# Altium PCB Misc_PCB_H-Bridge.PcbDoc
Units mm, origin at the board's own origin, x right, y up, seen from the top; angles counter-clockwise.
Board outline 25.4 x 30.58 mm, 2 copper layers (Top Layer, Bottom Layer); 16 components, 10 nets, 49 pads, 5 vias.
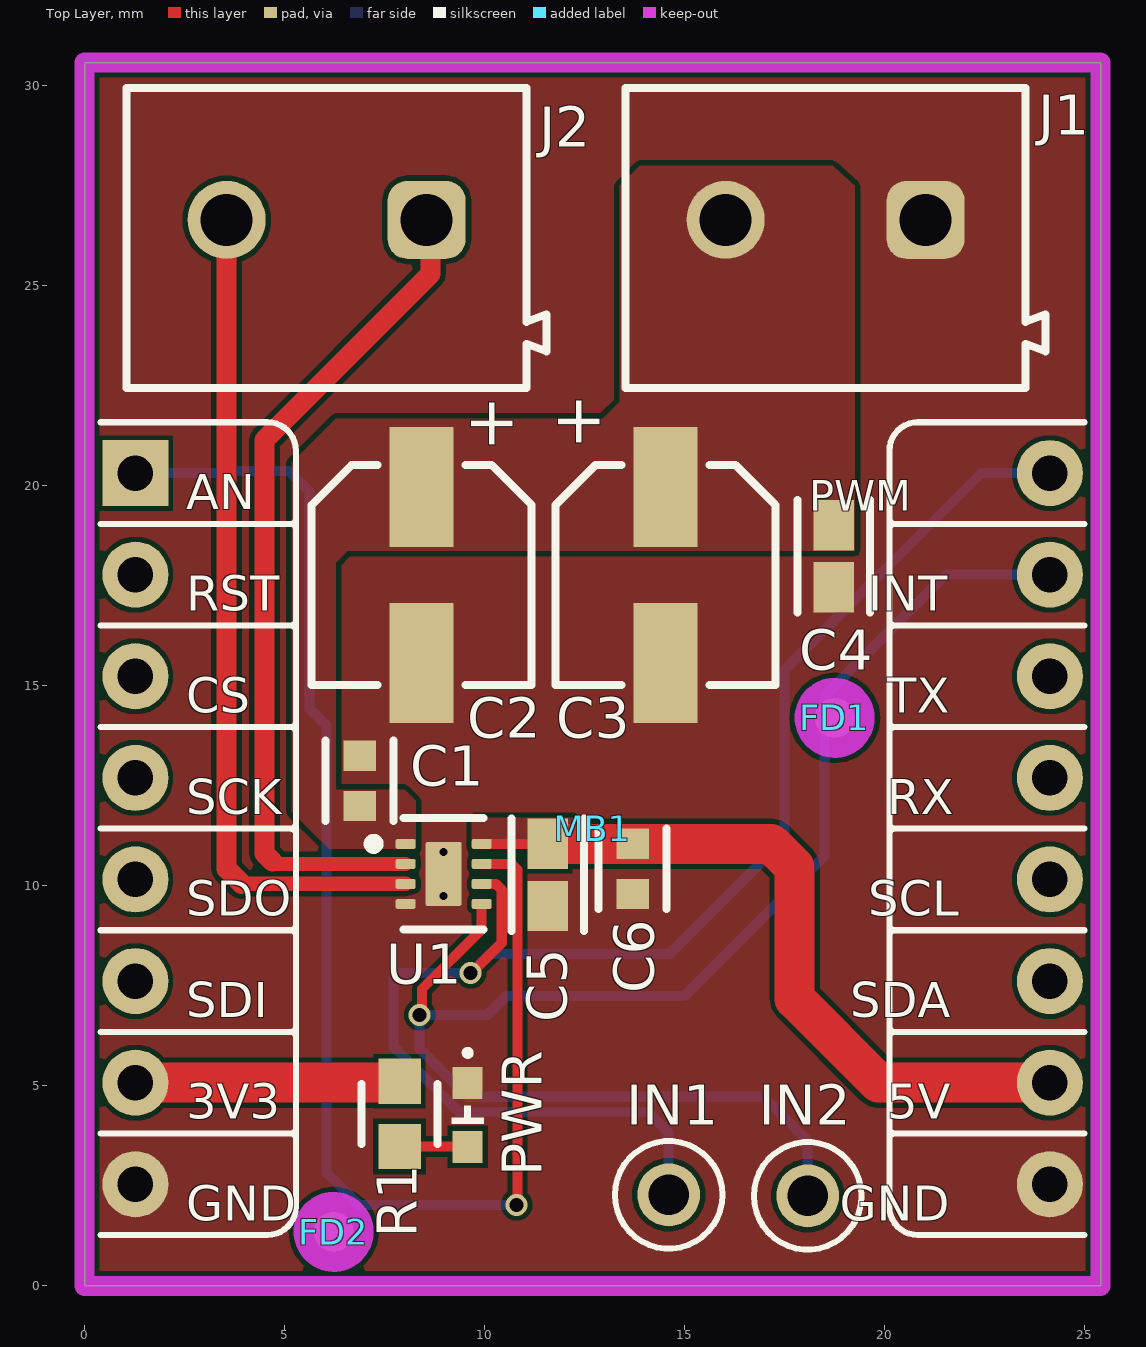
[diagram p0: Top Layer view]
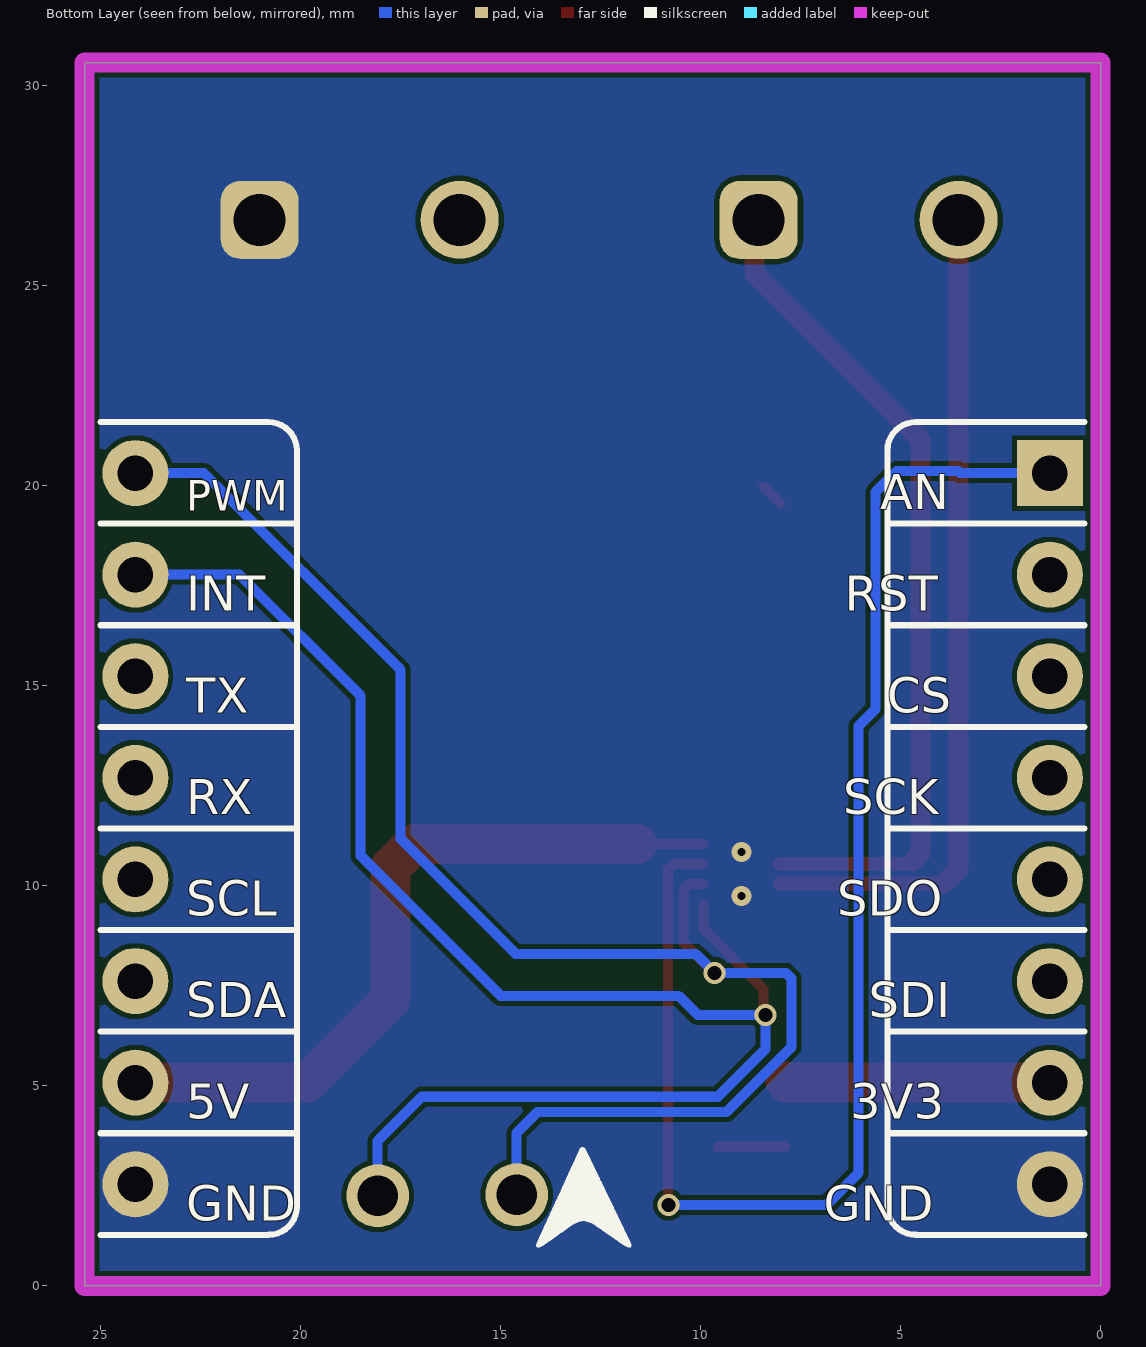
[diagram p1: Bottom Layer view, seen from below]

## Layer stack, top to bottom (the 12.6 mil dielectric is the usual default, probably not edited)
Top Solder: solder mask 0.0102, Solder Resist, Dk 3.5
Top Layer: signal copper 0.0356
Dielectric 1: dielectric 0.32, FR-4, Dk 4.8
Bottom Layer: signal copper 0.0356
Bottom Solder: solder mask 0.0102, Solder Resist, Dk 3.5

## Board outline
0,0 0,30.58 25.4,30.58 25.4,0

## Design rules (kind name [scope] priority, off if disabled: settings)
Clearance [All] p1: gap=0.125 ignorepadtopadclearanceinfootprint=FALSE
HoleSize HoleSizeVia [IsVia] p1: absolutevalues=TRUE maxlimit=0.45 minlimit=0.25 maxpercent=80.000 minpercent=20.000
HoleSize HoleSizePTH [IsPad] p2: absolutevalues=TRUE maxlimit=5.6 minlimit=0.5 maxpercent=80.000 minpercent=20.000
HoleToHoleClearance [All] p1: gap=0.3 allowstackedmicrovias=TRUE
MinimumAnnularRing MinimumAnnularRingVias [All] p1: minimumring=0.1
MinimumAnnularRing MinimumAnnularRingGeneral [All] p2: minimumring=0.3
MinimumSolderMaskSliver [All] p1: minsoldermaskwidth=0.08
PasteMaskExpansion [All] p1: expansion=0.085
PolygonConnect [All] p1: connectstyle=Direct reliefconductorwidth=0.254 reliefentries=4 polygonreliefangle="90 Angle" airgapwidth=0.254
RoutingVias [All] p1: holewidth=0.35 width=0.55 viastyle="Through Hole" minholewidth=0.3 minwidth=0.5 maxholewidth=0.45 maxwidth=0.65
SilkToSilkClearance SilkToSilkClerance [All] p1: silktosilkclearance=0.125
SilkToSolderMaskClearance [IsPad] p1: minsilkscreentomaskgap=0.125 clearancetoexposedcopper=TRUE
SolderMaskExpansion SolderMaskExpansionVia [IsVia] p1: expansion=0.1 istentingtop=TRUE useseparateexpansions=TRUE expansionbottom=0.1 istentingbottom=TRUE
SolderMaskExpansion [All] p2: expansion=0.075 istentingtop=FALSE
SupplyNets "Schematic Supply Nets_3" [InNet('VMotor')] p1: voltage=0.000
SupplyNets "Schematic Supply Nets_2" [InNet('+3V3')] p2: voltage=0.000
SupplyNets "Schematic Supply Nets_1" [InNet('GND')] p3: voltage=0.000
SupplyNets "Schematic Supply Nets" [InNet('+5')] p4: voltage=0.000
UnRoutedNet [All] p1: checkbadconnections=TRUE
Width [All] p1: maxlimit=2.54 minlimit=0.125 preferedwidth=0.254
23 further rules are at their usual default settings.

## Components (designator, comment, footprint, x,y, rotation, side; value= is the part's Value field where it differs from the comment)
C1 "4.7uF" FP-CL10-IPC_C 6.875,12.625 r90 top
C2 "10uF" WCAP-ASLI_D5H5.5 8.425,17.775 r90 top
C3 "10uF" WCAP-ASLI_D5H5.5 14.522,17.775 r90 top
C4 "0.1uF" FP-CC0603-DA-IPC_A 18.725,18.242 r90 top
C5 "0.1uF" FP-CC0603-DA-IPC_A 11.575,10.275 r90 top
C6 "4.7uF" FP-CL10-IPC_C 13.7,10.425 r270 top
FD1 "FID1X2R" FID1X2R 18.75,14.2 r0 top
FD2 "FID1X2R" FID1X2R 6.225,1.35 r90 top
IN1 "5001" FP-5001-MFG 14.6,2.275 r0 top
IN2 "5001" FP-5001-MFG 18.075,2.25 r90 top
J1 "691502710002" 691502710002 18.525,26.2 r180 top
J2 "691502710002" 691502710002 6.05,26.2 r180 top
MB1 "Embedd_Sensor_Schields" "Embedd_add_on_board_25,4 x 30,58" 0,0 r0 top locked
PWR "150060GS55040" WL-SMCD_0603 1279.575,-1265.725 r270 top (schematic designator PWR1)
R1 "33" FP-CRCW0603-e3-IPC_A 7.875,4.3 r90 top
U1 "DRV8210PDSGR" FP-DSG0008A-MFG 8.975,10.3 r0 top

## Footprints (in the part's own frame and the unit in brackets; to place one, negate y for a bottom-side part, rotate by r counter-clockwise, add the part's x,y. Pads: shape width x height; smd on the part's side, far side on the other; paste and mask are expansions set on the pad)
691502710002 [mm] "5,00mm - modular - Reflow compatible - Horizontal entry with pressure clamp - 02p"
  rrect50% 1.95x1.95 hole 1.3: 1(-2.5,-0.45)
  round 1.95 hole 1.3: 2(2.5,-0.45)
  silkscreen extent -5.5,-3.75 5,3.75, body extent -5.5,-3.75 5,3.75, height 10.1
"Embedd_add_on_board_25,4 x 30,58" [mil] "Medium footprint"
  rect 65x65 hole 35: 1(50,800)
  round 65 hole 35: 2(50,700) 3(50,600) 4(50,500) 5(50,400) 6(50,300) 7(50,200) 8(50,100) 9(950,100) 10(950,200) 11(950,300) 12(950,400) 13(950,500) 14(950,600) 15(950,700) 16(950,800)
  silkscreen extent 16,50 984,850, body extent 0,51 1000,851, height 103
FID1X2R [mm] "Fiducial - Round 1x2mm"
  round 1 smd mask-2539.97: 1(0,0)
  Top Layer keep-out circle w1: c0,0 r0.5
FP-5001-MFG [mm]
  round 1.57 hole 1.016 paste-2539.97 mask+0: 1(0,0)
  silkscreen extent -1.35,-1.34 1.35,1.34, body extent -1.45,-1.45 1.45,1.45, height 0.25
FP-CC0603-DA-IPC_A [mm]
  rect 1.258x1.012 smd paste+0 mask+0: 1(-0.777,0) 2(0.777,0)
  silkscreen extent -1.41,-0.91 1.41,0.91, body extent -1.91,-1.01 1.91,1.01, height 0.25
FP-CL10-IPC_C [mm]
  rect 0.758x0.812 smd paste+0 mask+0: 1(-0.627,0) 2(0.627,0)
  silkscreen extent -1.01,-0.85 1.01,0.85, body extent -1.11,-0.55 1.11,0.55, height 0.25
FP-CRCW0603-e3-IPC_A [mm]
  rect 1.135x1.062 smd paste+0 mask+0: 1(-0.815,0) 2(0.815,0)
  silkscreen extent -0.75,-0.95 0.75,0.95, body extent -1.88,-1.03 1.88,1.03, height 0.25
FP-DSG0008A-MFG [mm]
  rrect40% 0.5x0.25 smd paste+0 mask+0: 1(-0.95,0.75) 2(-0.95,0.25) 3(-0.95,-0.25) 4(-0.95,-0.75) 5(0.95,-0.75) 6(0.95,-0.25) 7(0.95,0.25) 8(0.95,0.75)
  rrect11% 0.9x1.6 smd paste-1000 mask+0: 9(0,0)
  silkscreen extent -1.87,-1.39 1,1.4, body extent -1.3,-1.15 1.3,1.15, height 0.25
WCAP-ASLI_D5H5.5 [mm] "Aluminium Electrolytic V-Chip SMT Capacitors, 5x5.5mm"
  rect 3x1.6 smd: 1(2.2,0) 2(-2.2,0)
  silkscreen extent -2.75,-2.75 2.75,2.75, body extent -3,-2.65 3,2.65, height 5.5
WL-SMCD_0603 [mm] "SMD Mono-color Chip LED, body 1.6x0.8mm"
  rect 0.8x0.75 smd: 1(-1270.8,-1270) 2(-1269.2,-1270)
  silkscreen extent -1271.62,-1270.4 -1269.78,-1269.6, body extent -1270.8,-1270.4 -1269.2,-1269.6, height 0.42

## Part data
C1 C6: library part CMP-13271-003017-1, "Cap Ceramic 4.7uF 10V X5R ±10% Pad SMD 0603 +85°C T/R", Case Code (Imperial)=0603, Case Code (Metric)=1608, Dielectric=X5R, Max Operating Temperature=85°C, Min Operating Temperature=-55°C, Package Quantity=1, Tolerance=10%, Voltage Rating=10V
C2 C3: library part CMP-03913-53914615-1, "865080642006 WCAP-ASLI Aluminum Electrolytic Capacitors", Capacitance=10µF, Case/Package=Radial, ESR (Equivalent Series Resistance)=1.63932Ω, Insulation Resistance=10MΩ, Leakage Current=5µA, Max Operating Temperature=105°C, Min Operating Temperature=-55°C, Ripple Current=95mA, Tolerance=20%, Voltage Rating=50V
C4 C5: library part CMP-03422-001490-1, "CAP CER 0.1UF 50V X7R 0603", Capacitance=100nF, Case Code (Imperial)=0603, Case Code (Metric)=1608, Dielectric=X7R, Max Operating Temperature=125°C, Min Operating Temperature=-55°C, Resistor Type=Ceramic, Tolerance=5%, Voltage Rating=50V
FD1 FD2: library part CMP-00028-00005-4, "Fiducial - Round 1x2mm"
IN1 IN2: library part CMP-2000-05181-2, "PC TEST POINT MINIATURE BLACK", Color=Black, Flammability Rating="UL94 V-0", Package Quantity=100
J1 J2: library part CMP-1502-03333-2, Max Operating Temperature=130°C, Min Operating Temperature=-45°C
MB1: library part CMP-00030-00005-3, "Footprint for sensor shields", Max Operating Temperature=85°C, Min Operating Temperature=-40°C
PWR: library part CMP-03913-90235563-2, "150060GS55040 WL-SMCD SMT Mono-color Chip LED Diffused", Forward Current=60mA, Forward Voltage=3.2V, Max Operating Temperature=85°C, Max Reverse Voltage (DC)=5V, Min Operating Temperature=-40°C
R1: library part CMP-2000-03250-2, "RES Thick Film, 33Ω, 1%, 0.1W, 100ppm/°C, 0603", Case Code (Imperial)=0603, Case Code (Metric)=1608, Max Operating Temperature=155°C, Max Power Dissipation=100mW, Min Operating Temperature=-55°C, Package Quantity=10, Resistance=33R, Temperature Coefficient=100ppm/°C, Tolerance=1%, Voltage Rating=75V
U1: library part CMP-04915-000081-1, "11V, 1A H-BRIDGE MOTOR DRIVER, P"

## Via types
v1: diameter 0.55, hole 0.35, Top Layer to Bottom Layer, tented both sides, 3 vias
v2: diameter 0.5, hole 0.2, Top Layer to Bottom Layer, 2 vias

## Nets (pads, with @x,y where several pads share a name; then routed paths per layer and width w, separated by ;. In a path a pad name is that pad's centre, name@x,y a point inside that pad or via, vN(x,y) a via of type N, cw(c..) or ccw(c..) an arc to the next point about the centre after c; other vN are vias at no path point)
+3V3: MB1.7 R1.2 | length 6.6
  Top Layer w1: MB1.7 7.844,5.08 7.875,5.111 R1.2
+5: C5.2 C6.1 MB1.10 U1.8 | length 18.6
  Top Layer w0.254: U1.8 C5.2@11.573,11.05
  Top Layer w1: C5.2@11.573,11.05 C5.2 C6.1 17.164,11.052 17.75,10.466 17.75,7.175 19.845,5.08 MB1.10
GND: C1.2 C2.2 C3.2 C4.1 C5.1 C6.2 J1.1 MB1.8 MB1.9 PWR.1 U1.4 U1.9
  other v2: 8.975,9.75 8.975,10.85
IN1: IN1.1 MB1.16 U1.6 | length 38.1
  Top Layer w0.254: v1(9.65,7.825) 9.675,7.825 10.426,8.576 10.426,9.349 ; U1.6 10.277,10.05 10.427,9.9 10.427,9.35
  Bottom Layer w0.254: IN1.1 14.6,3.825 14.075,4.35 9.35,4.35 7.725,5.975 7.725,7.676 7.874,7.825 v1(9.65,7.825) 10.125,8.3 14.625,8.3 17.5,11.175 17.5,15.4 22.42,20.32 MB1.16
IN2: IN2.1 MB1.15 U1.5 | length 39
  Top Layer w0.254: v1(8.375,6.775) 8.432,6.832 8.432,7.421 9.925,8.914 U1.5
  Bottom Layer w0.254: IN2.1 18.075,3.625 16.971,4.729 9.571,4.729 8.375,5.925 v1(8.375,6.775) 10.075,6.775 10.55,7.25 15,7.25 18.5,10.75 18.5,14.75 21.53,17.78 MB1.15
Motor_OUT1: J2.1 U1.2 | length 21.2
  Top Layer w0.35: 4.7,10.605 4.755,10.55 U1.2
  Top Layer w0.5: 4.7,10.605 4.5,10.805 4.5,21.15 8.65,25.3 J2.1@8.65,26.65
Motor_OUT2: J2.2 U1.3 | length 20.9
  Top Layer w0.36: 3.925,10.05 U1.3
  Top Layer w0.5: J2.2 3.55,10.425 3.925,10.05
NetPWR_2: PWR.2 R1.1 | length 1.7
  Top Layer w0.254: R1.1 9.565,3.485 PWR.2
SLEEP: MB1.1 U1.7 | length 36.2
  Top Layer w0.254: U1.7 10.668,10.55 10.817,10.401 10.817,2.042 v1(10.8,2.025)
  Bottom Layer w0.254: MB1.1 3.512,20.32 3.562,20.37 5.105,20.37 5.625,19.85 5.625,14.425 6.05,14 6.05,2.825 6.85,2.025 v1(10.8,2.025)
VMotor: C1.1 C2.1 C3.1 C4.2 J1.2 U1.1 | length 0.6
  Top Layer w0.254: C2.1@8,19.55 C2.1
pads on no net: FD1.1 FD2.1 MB1.2 MB1.3 MB1.4 MB1.5 MB1.6 MB1.11 MB1.12 MB1.13 MB1.14

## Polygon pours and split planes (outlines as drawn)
GND on Top Layer "GND_L01_P005" (solid, remove dead copper, pour order 5): 0,0 0,30.58 25.4,30.58 25.4,0
+5 on Top Layer "NONET_L-01_P-001" (solid, remove dead copper, pour order 4): 9.7,10.925 9.675,10.95 9.675,11.625 9.75,11.7 12.225,11.7 12.225,11.1 12.05,10.925
VMotor on Top Layer "Top Layer-VMotor" (solid, remove dead copper, pour order 0): 6.275,18.075 6.575,18.375 19.25,18.375 19.25,27.5 18.7,28 13.875,28 13.375,27.5 13.375,22.1 12.95,21.675 6.275,21.675 5.175,20.575 5.175,11.85 6.1,10.925 8.275,10.925 8.275,12.125 8,12.4 6.275,12.4
GND on Bottom Layer "GND_L02_P001" (solid, remove dead copper, pour order 1): 0,0 0,30.58 25.4,30.58 25.4,0

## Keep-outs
Keep-Out Layer:
  the board outline again, w0.5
